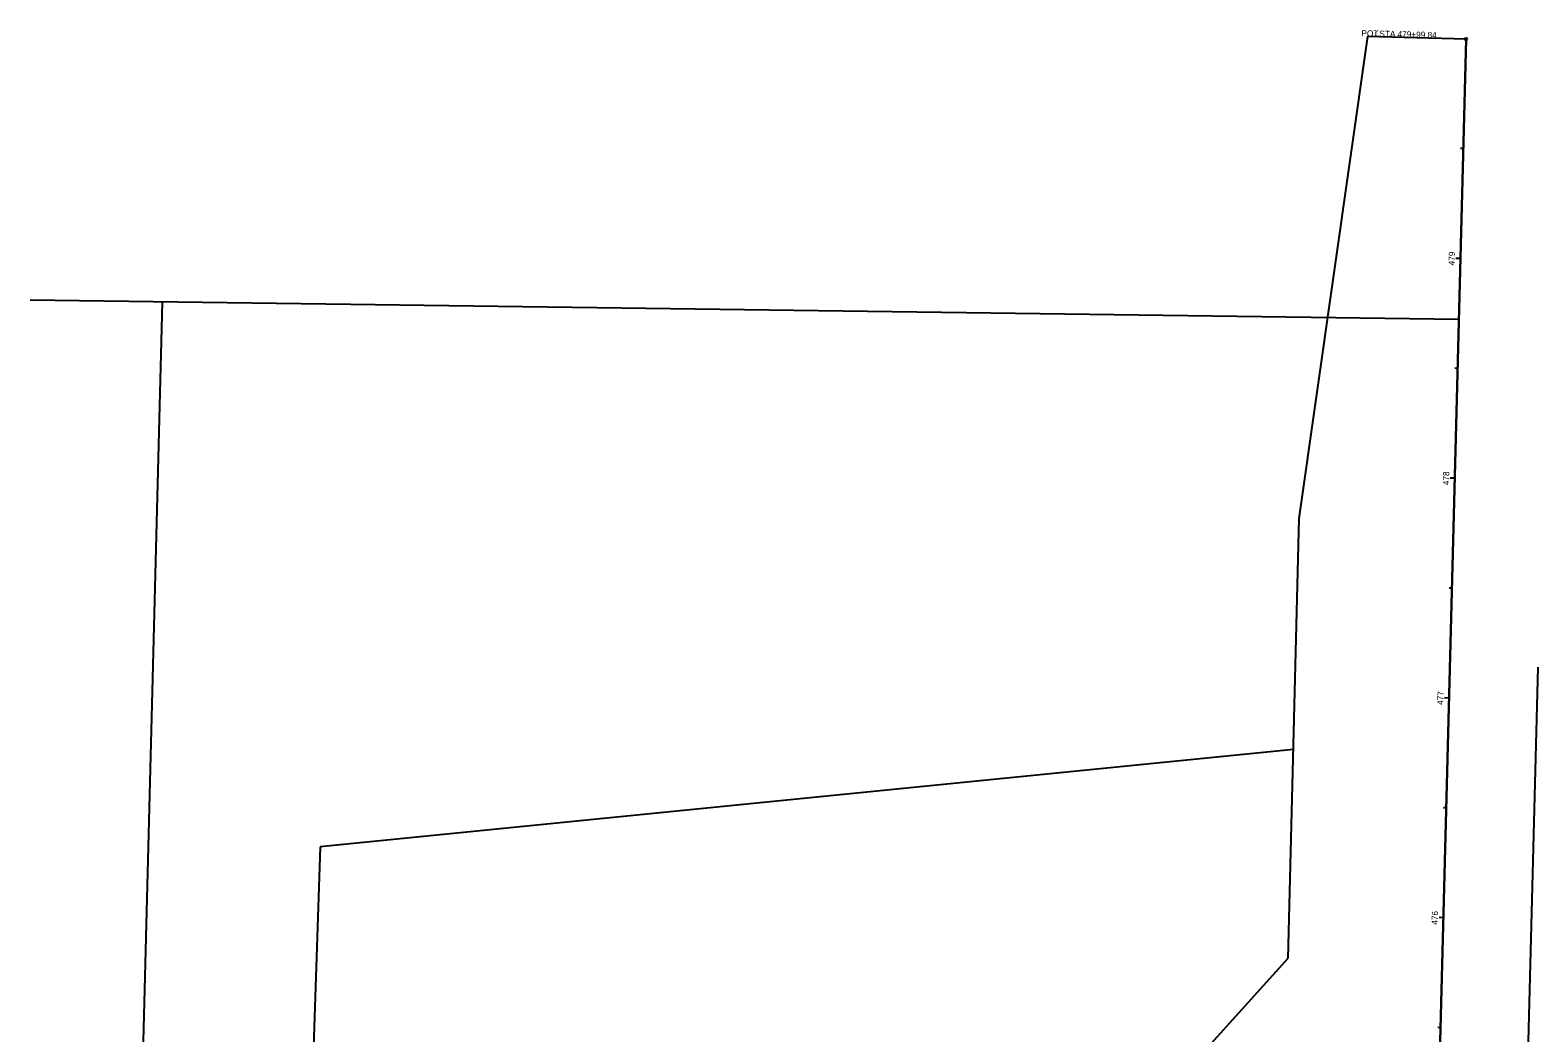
# Model space of a CAD drawing. Extents: x 1390087 to 1393932, y 303908 to 305061.
# Drawn here: x 1391697 to 1392382, y 304605 to 305061 of the extents above; entities that cross this region are included whole.
import ezdxf

# ---------------------------------------------------------------- set-up
doc = ezdxf.new("R2010")
doc.units = 0
for name, color, linetype in [('DV_X_Property_Line', 7, 'Continuous'), ('DV_X_Section_VMS_Line', 7, 'Continuous'), ('RW_X_CL', 7, 'Continuous'), ('RW_X_CL_100_Cardinal_Points', 7, 'Continuous'), ('RW_X_CL_100_Stations', 7, 'Continuous'), ('RW_X_Esmt_SH', 7, 'Continuous')]:
    doc.layers.add(name, color=color, linetype=linetype)

msp = doc.modelspace()

# ---------------------------------------------------------------- linework, layer by layer
at = {"layer": 'DV_X_Property_Line'}
for p, q in [((1392346.44, 304929.17), (1391696.76, 304937.88)), ((1391756.75, 304937.07), (1391742.54, 304379.08)), ((1392271.24, 304733.61), (1391828.58, 304689.27)), ((1391828.58, 304689.27), (1391818.54, 304388.2))]:
    msp.add_line(p, q, dxfattribs=at)
at = {"layer": 'DV_X_Section_VMS_Line'}
msp.add_line((1392349.72, 305056.71), (1392320.18, 303908.29), dxfattribs=at)
at = {"layer": 'RW_X_CL'}
for p, q in [((1392349.72, 305056.71), (1392320.18, 303908.29)), ((1392320.18, 303908.29), (1392349.72, 305056.71))]:
    msp.add_line(p, q, dxfattribs=at)
at = {"layer": 'RW_X_CL_100_Cardinal_Points'}
msp.add_line((1392349.72, 305056.71), (1392304.74, 305057.86), dxfattribs=at)
msp.add_circle((1392349.72, 305056.71), 0.6, dxfattribs=at)
at = {"layer": 'RW_X_CL_100_Stations'}
for p, q in [((1392348.44, 305006.88), (1392347.24, 305006.91)), ((1392347.16, 304956.9), (1392345.16, 304956.95)), ((1392345.87, 304906.91), (1392344.67, 304906.94)), ((1392344.59, 304856.93), (1392342.59, 304856.98)), ((1392343.3, 304806.94), (1392342.1, 304806.98)), ((1392342.01, 304756.96), (1392340.01, 304757.01)), ((1392340.73, 304706.98), (1392339.53, 304707.01)), ((1392339.44, 304656.99), (1392337.44, 304657.05)), ((1392338.16, 304607.01), (1392336.96, 304607.04))]:
    msp.add_line(p, q, dxfattribs=at)
at = {"layer": 'RW_X_Esmt_SH'}
for p, q in [((1392273.9, 304838.57), (1392305.1, 305057.85)), ((1392268.84, 304638.64), (1392273.9, 304838.57)), ((1392382.39, 304771.01), (1392377.37, 304575.85)), ((1392165.07, 304523.87), (1392268.84, 304638.64))]:
    msp.add_line(p, q, dxfattribs=at)

# ---------------------------------------------------------------- texts
at = {"layer": 'RW_X_CL_100_Cardinal_Points'}
for s, p in [('POT', (1392302.13, 305057.97)), (' STA. ', (1392309.26, 305057.78)), ('479+99.84', (1392318.57, 305057.54))]:
    msp.add_text(s, height=2.8, rotation=358.52651, dxfattribs=at).set_placement(p)
at = {"layer": 'RW_X_CL_100_Stations'}
for s, p in [('479', (1392344.57, 304953.73)), ('478', (1392342, 304853.74)), ('477', (1392339.43, 304753.78)), ('476', (1392336.86, 304653.8))]:
    msp.add_text(s, height=2.8, rotation=88.52651, dxfattribs=at).set_placement(p)

doc.saveas('drawing.dxf')
